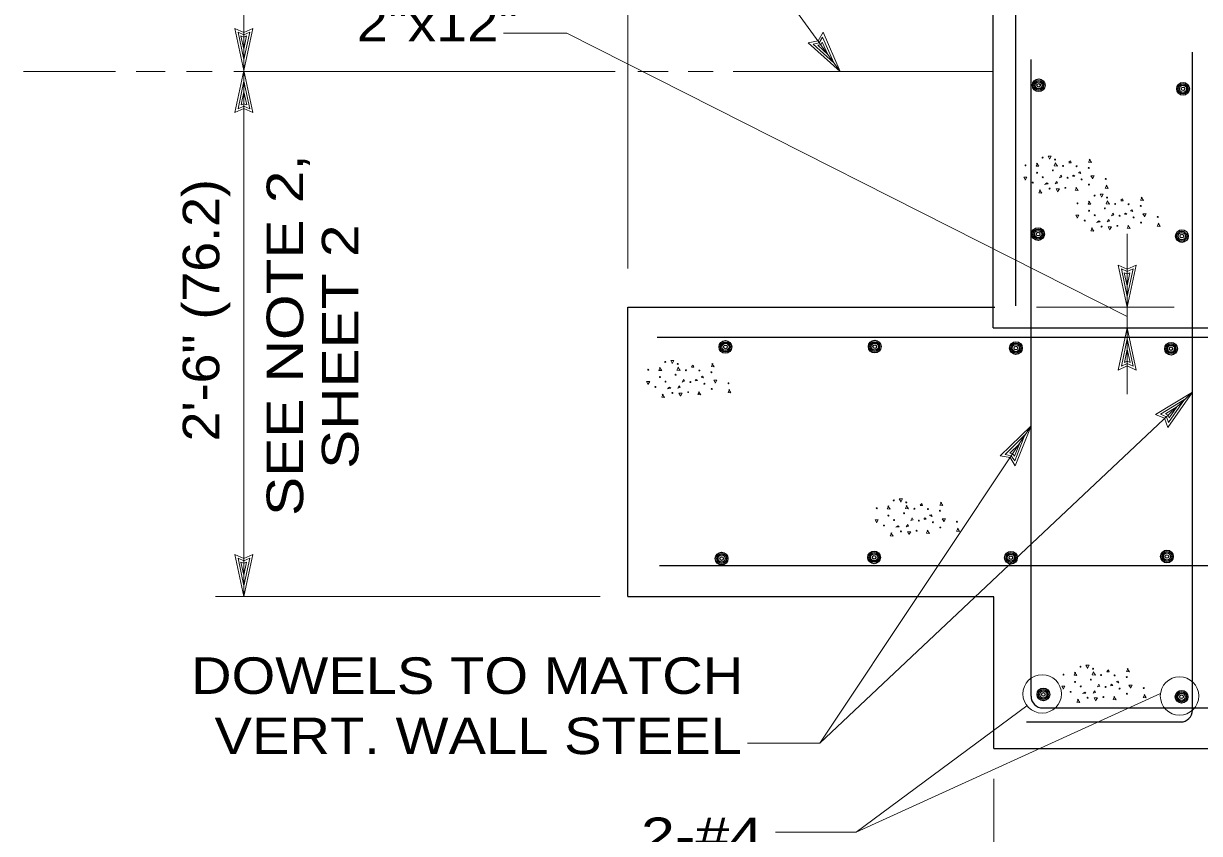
# Model space of a CAD drawing. Extents: x -28.1 to 13.9, y -16.1 to 13.9.
# Drawn here: x -10.95 to -6.926, y -12.515 to -9.744 of the extents above; entities that cross this region are included whole.
import ezdxf
from ezdxf.enums import TextEntityAlignment as Align

# ---------------------------------------------------------------- set-up
doc = ezdxf.new("R2010")
doc.units = 0
doc.header["$LTSCALE"] = 0.05
doc.layers.add('1', color=7, linetype='Continuous', lineweight=13)
doc.layers.add('2', color=7, linetype='Continuous', lineweight=13)

msp = doc.modelspace()

# ---------------------------------------------------------------- linework, layer by layer
at = {"layer": '1', "lineweight": 25}
for p, q in [((-7.63204, -10.78531), (-7.63204, -2.71131)), ((-7.55404, -10.70931), (-7.55404, -2.79231)), ((-6.95004, -12.09331), (-6.95004, -9.84231)), ((-7.50204, -12.04531), (-7.50204, -9.86731)), ((-8.88204, -11.70431), (-8.88204, -10.71431)), ((-8.88204, -10.71431), (-7.62604, -10.71431)), ((-8.78204, -10.81631), (-2.84404, -10.81631)), ((-7.63204, -10.78531), (-6.79104, -10.78531)), ((-8.77404, -11.59831), (-2.84304, -11.59831)), ((-8.88204, -11.70431), (-7.62904, -11.70431)), ((-7.62904, -12.22431), (-7.62904, -11.70531)), ((-7.46204, -12.08531), (-6.89104, -12.08531)), ((-7.51804, -12.13331), (-6.99004, -12.13331)), ((-7.62904, -12.22431), (-6.78704, -12.22431))]:
    msp.add_line(p, q, dxfattribs=at)
at = {"layer": '1'}
for p, q in [((-8.88204, -10.58231), (-8.88204, -7.58031)), ((-9.01904, -8.71531), (-8.15504, -9.90831)), ((-10.19604, -9.90431), (-10.22704, -9.76031)), ((-10.19604, -9.86731), (-10.21604, -9.77331)), ((-10.21604, -9.77331), (-10.19604, -9.78231)), ((-10.19604, -9.90431), (-10.16504, -9.76031)), ((-10.19604, -9.86731), (-10.17604, -9.77331)), ((-10.19604, -9.78231), (-10.17604, -9.77331)), ((-9.30704, -9.77731), (-9.09104, -9.77731)), ((-9.09104, -9.77731), (-7.17304, -10.74631)), ((-8.15504, -9.90831), (-8.21404, -9.77331)), ((-10.19604, -9.83131), (-10.20604, -9.78631)), ((-10.20604, -9.78631), (-10.19604, -9.79031)), ((-10.19604, -9.83131), (-10.18704, -9.78631)), ((-10.19604, -9.79031), (-10.18704, -9.78631)), ((-8.15504, -9.90831), (-8.26504, -9.81031)), ((-8.24804, -9.81431), (-8.22704, -9.80931)), ((-8.17704, -9.87831), (-8.24804, -9.81431)), ((-8.23204, -9.81831), (-8.22204, -9.81631)), ((-8.19804, -9.84931), (-8.23204, -9.81831)), ((-8.22704, -9.80931), (-8.21604, -9.79031)), ((-8.22204, -9.81631), (-8.21704, -9.80731)), ((-8.19804, -9.84931), (-8.21704, -9.80731)), ((-8.17704, -9.87831), (-8.21604, -9.79031)), ((-10.63504, -9.90831), (-10.95004, -9.90831)), ((-10.46504, -9.90831), (-10.56504, -9.90831)), ((-10.30404, -9.90831), (-10.39204, -9.90831)), ((-8.92504, -9.90831), (-10.23004, -9.90831)), ((-10.19604, -9.90431), (-10.22704, -10.04831)), ((-10.19604, -9.90431), (-10.16504, -10.04831)), ((-8.74404, -9.90831), (-8.84804, -9.90831)), ((-8.59004, -9.90831), (-8.67504, -9.90831)), ((-7.63204, -9.90831), (-8.52104, -9.90831)), ((-10.19604, -9.94131), (-10.21604, -10.03531)), ((-10.19604, -9.97731), (-10.20504, -10.02231)), ((-10.19604, -9.94131), (-10.17604, -10.03531)), ((-10.19604, -9.97731), (-10.18604, -10.02231)), ((-10.19604, -10.01831), (-10.20504, -10.02231)), ((-10.18604, -10.02231), (-10.19604, -10.01831)), ((-10.19604, -10.02631), (-10.21604, -10.03531)), ((-10.17604, -10.03531), (-10.19604, -10.02631)), ((-7.17304, -10.71431), (-7.20404, -10.57031)), ((-7.17304, -10.67731), (-7.19304, -10.58331)), ((-7.19304, -10.58331), (-7.17304, -10.59231)), ((-7.17304, -10.71431), (-7.14204, -10.57031)), ((-7.17304, -10.67731), (-7.15304, -10.58331)), ((-7.17304, -10.59231), (-7.15304, -10.58331)), ((-7.17304, -10.64131), (-7.18304, -10.59631)), ((-7.18304, -10.59631), (-7.17304, -10.60031)), ((-7.17304, -10.64131), (-7.16404, -10.59631)), ((-7.17304, -10.60031), (-7.16404, -10.59631)), ((-7.48304, -10.71431), (-7.01204, -10.71431)), ((-7.17304, -10.78531), (-7.20404, -10.92931)), ((-7.17304, -10.82231), (-7.19304, -10.91631)), ((-7.17304, -10.78531), (-7.14204, -10.92931)), ((-7.17304, -10.82231), (-7.15304, -10.91631)), ((-7.17304, -10.85831), (-7.18204, -10.90331)), ((-7.17304, -10.85831), (-7.16304, -10.90331)), ((-7.17304, -10.89931), (-7.18204, -10.90331)), ((-7.16304, -10.90331), (-7.17304, -10.89931)), ((-7.17304, -10.90731), (-7.19304, -10.91631)), ((-7.15304, -10.91631), (-7.17304, -10.90731)), ((-6.95004, -11.00531), (-8.22504, -12.20531)), ((-6.95004, -11.00531), (-7.07604, -11.08131)), ((-6.95004, -11.00531), (-7.03404, -11.12631)), ((-6.97704, -11.03031), (-7.05904, -11.08031)), ((-7.00304, -11.05531), (-7.04204, -11.07931)), ((-6.97704, -11.03031), (-7.03204, -11.10931)), ((-7.00304, -11.05531), (-7.02904, -11.09331)), ((-7.03904, -11.08931), (-7.05904, -11.08031)), ((-7.03304, -11.08331), (-7.04204, -11.07931)), ((-7.03204, -11.10931), (-7.03904, -11.08931)), ((-7.02904, -11.09331), (-7.03304, -11.08331)), ((-7.50204, -11.12031), (-7.60804, -11.22331)), ((-7.50204, -11.12031), (-7.55604, -11.25731)), ((-7.52304, -11.15131), (-7.59104, -11.21831)), ((-7.54204, -11.18131), (-7.57504, -11.21331)), ((-7.54204, -11.18131), (-7.55904, -11.22431)), ((-7.52304, -11.15131), (-7.55804, -11.24031)), ((-7.57004, -11.22231), (-7.59104, -11.21831)), ((-7.56504, -11.21531), (-7.57504, -11.21331)), ((-7.55804, -11.24031), (-7.57004, -11.22231)), ((-7.55904, -11.22431), (-7.56504, -11.21531)), ((-10.19604, -11.70431), (-10.22704, -11.56031)), ((-10.19604, -11.66731), (-10.21604, -11.57331)), ((-10.21604, -11.57331), (-10.19604, -11.58231)), ((-10.19604, -11.63131), (-10.20604, -11.58631)), ((-10.20604, -11.58631), (-10.19604, -11.59031)), ((-10.19604, -11.70431), (-10.16504, -11.56031)), ((-10.19604, -11.66731), (-10.17604, -11.57331)), ((-10.19604, -11.58231), (-10.17604, -11.57331)), ((-10.19604, -11.63131), (-10.18704, -11.58631)), ((-10.19604, -11.59031), (-10.18704, -11.58631)), ((-8.97704, -11.70431), (-10.29304, -11.70431)), ((-7.05904, -12.03631), (-8.10004, -12.51031)), ((-7.51604, -12.07831), (-8.10004, -12.51031)), ((-7.62904, -12.32831), (-7.62904, -12.78131)), ((-8.10004, -12.51031), (-8.37704, -12.51031))]:
    msp.add_line(p, q, dxfattribs=at)
for points in [[(-10.19604, -11.70431), (-10.19604, -9.90431), (-10.19604, -2.71031)], [(-10.22704, -9.76031), (-10.19604, -9.77431), (-10.16504, -9.76031)], [(-8.26504, -9.81031), (-8.23104, -9.80331), (-8.21404, -9.77331)], [(-10.16504, -10.04831), (-10.19604, -10.03431), (-10.22704, -10.04831)], [(-7.17304, -11.01231), (-7.17304, -10.78531), (-7.17304, -10.71431), (-7.17304, -10.46331)], [(-7.20404, -10.57031), (-7.17304, -10.58431), (-7.14204, -10.57031)], [(-7.14204, -10.92931), (-7.17304, -10.91531), (-7.20404, -10.92931)], [(-7.03404, -11.12631), (-7.04504, -11.09431), (-7.07604, -11.08131)], [(-7.50204, -11.12031), (-8.22504, -12.20531), (-8.47204, -12.20531)], [(-7.55604, -11.25731), (-7.57404, -11.22831), (-7.60804, -11.22331)], [(-10.22704, -11.56031), (-10.19604, -11.57431), (-10.16504, -11.56031)]]:
    msp.add_lwpolyline(points, dxfattribs=at)
at = {"layer": '1', "lineweight": 25}
for centre, radius in [((-7.47599, -9.95523), 0.02168), ((-7.47599, -9.95523), 0.01681), ((-7.47599, -9.95523), 0.01233), ((-7.47599, -9.95523), 0.00623), ((-6.98199, -9.96723), 0.02168), ((-6.98199, -9.96723), 0.01681), ((-6.98199, -9.96723), 0.01233), ((-6.98199, -9.96723), 0.00623), ((-7.47799, -10.46423), 0.02168), ((-7.47799, -10.46423), 0.01681), ((-7.47799, -10.46423), 0.01233), ((-7.47799, -10.46423), 0.00623), ((-6.98599, -10.47123), 0.02168), ((-6.98599, -10.47123), 0.01681), ((-6.98599, -10.47123), 0.01233), ((-6.98599, -10.47123), 0.00623), ((-8.54799, -10.85023), 0.02168), ((-8.54799, -10.85023), 0.01681), ((-8.54799, -10.85023), 0.01233), ((-8.54799, -10.85023), 0.00623), ((-8.03699, -10.84923), 0.02168), ((-8.03699, -10.84923), 0.01681), ((-8.03699, -10.84923), 0.01233), ((-8.03699, -10.84923), 0.00623), ((-7.55399, -10.85423), 0.02168), ((-7.55399, -10.85423), 0.01681), ((-7.55399, -10.85423), 0.01233), ((-7.55399, -10.85423), 0.00623), ((-7.02299, -10.85623), 0.02168), ((-7.02299, -10.85623), 0.01681), ((-7.02299, -10.85623), 0.01233), ((-7.02299, -10.85623), 0.00623), ((-8.03899, -11.57023), 0.02168), ((-7.57099, -11.57123), 0.02168), ((-7.03699, -11.56723), 0.02168), ((-8.56099, -11.57423), 0.02168), ((-8.56099, -11.57423), 0.01681), ((-8.56099, -11.57423), 0.01233), ((-8.56099, -11.57423), 0.00623), ((-8.03899, -11.57023), 0.01681), ((-8.03899, -11.57023), 0.01233), ((-8.03899, -11.57023), 0.00623), ((-7.57099, -11.57123), 0.01681), ((-7.57099, -11.57123), 0.01233), ((-7.57099, -11.57123), 0.00623), ((-7.03699, -11.56723), 0.01681), ((-7.03699, -11.56723), 0.01233), ((-7.03699, -11.56723), 0.00623), ((-7.45999, -12.03923), 0.02168), ((-7.45999, -12.03923), 0.01681), ((-7.45999, -12.03923), 0.01233), ((-6.98699, -12.04723), 0.02168), ((-6.98699, -12.04723), 0.01681), ((-7.45999, -12.03923), 0.00623), ((-6.98699, -12.04723), 0.01233), ((-6.98699, -12.04723), 0.00623)]:
    msp.add_circle(centre, radius, dxfattribs=at)
at = {"layer": '1'}
for centre in [(-7.46404, -12.03731), (-6.99404, -12.04431)]:
    msp.add_circle(centre, 0.0658, dxfattribs=at)
at = {"layer": '1', "lineweight": 25}
for centre, start, end in [((-7.46204, -12.04531), 180, 270), ((-6.99004, -12.09331), 270, 0)]:
    msp.add_arc(centre, 0.04, start, end, dxfattribs=at)
at = {"layer": '2'}
for p, q in [((-7.37304, -10.21831), (-7.36704, -10.21331)), ((-7.19504, -10.34831), (-7.18904, -10.34331)), ((-8.66404, -10.91731), (-8.65804, -10.91231)), ((-7.88204, -11.39131), (-7.87604, -11.38631)), ((-7.24304, -11.96031), (-7.23704, -11.95531))]:
    msp.add_line(p, q, dxfattribs=at)
for points in [[(-7.48004, -10.22131), (-7.48504, -10.23131), (-7.47504, -10.23231), (-7.48304, -10.22131)], [(-7.43904, -10.20631), (-7.44404, -10.19731), (-7.43304, -10.19731), (-7.43904, -10.20831)], [(-7.41804, -10.22031), (-7.42304, -10.23031), (-7.41204, -10.23131), (-7.42004, -10.22031)], [(-7.36704, -10.21331), (-7.36504, -10.22031), (-7.37304, -10.22031)], [(-7.30004, -10.20831), (-7.30504, -10.21831), (-7.29504, -10.21931), (-7.30304, -10.20831)], [(-7.34004, -10.25331), (-7.33504, -10.25131), (-7.33204, -10.25731), (-7.34004, -10.25431)], [(-7.52204, -10.27731), (-7.52704, -10.26931), (-7.51604, -10.26931), (-7.52204, -10.27931)], [(-7.45304, -10.29231), (-7.44804, -10.28931), (-7.44404, -10.29231), (-7.45604, -10.29431)], [(-7.36004, -10.26631), (-7.35704, -10.26231), (-7.35204, -10.26631), (-7.35904, -10.26731)], [(-7.29204, -10.27331), (-7.29704, -10.26531), (-7.28604, -10.26531), (-7.29204, -10.27531)], [(-7.24304, -10.29731), (-7.24804, -10.30731), (-7.23804, -10.30831), (-7.24504, -10.29731)], [(-7.47004, -10.31331), (-7.47504, -10.32331), (-7.46504, -10.32431), (-7.47304, -10.31331)], [(-7.41104, -10.31831), (-7.41604, -10.30931), (-7.40504, -10.30931), (-7.41104, -10.31931)], [(-7.34604, -10.30431), (-7.35104, -10.31431), (-7.34104, -10.31531), (-7.34904, -10.30431)], [(-7.26104, -10.33631), (-7.26604, -10.32731), (-7.25504, -10.32731), (-7.26104, -10.33831)], [(-7.12204, -10.33831), (-7.12704, -10.34831), (-7.11704, -10.34931), (-7.12504, -10.33831)], [(-7.30204, -10.35131), (-7.30704, -10.36131), (-7.29704, -10.36231), (-7.30504, -10.35131)], [(-7.24004, -10.35031), (-7.24504, -10.36031), (-7.23404, -10.36131), (-7.24204, -10.35031)], [(-7.18904, -10.34331), (-7.18704, -10.35031), (-7.19504, -10.35031)], [(-7.16204, -10.38331), (-7.15704, -10.38131), (-7.15404, -10.38731), (-7.16204, -10.38431)], [(-7.34404, -10.40731), (-7.34904, -10.39931), (-7.33804, -10.39931), (-7.34404, -10.40931)], [(-7.27504, -10.42231), (-7.27004, -10.41931), (-7.26604, -10.42231), (-7.27804, -10.42431)], [(-7.18204, -10.39631), (-7.17904, -10.39231), (-7.17404, -10.39631), (-7.18104, -10.39731)], [(-7.11404, -10.40331), (-7.11904, -10.39531), (-7.10804, -10.39531), (-7.11404, -10.40531)], [(-7.29204, -10.44331), (-7.29704, -10.45331), (-7.28704, -10.45431), (-7.29504, -10.44331)], [(-7.23304, -10.44831), (-7.23804, -10.43931), (-7.22704, -10.43931), (-7.23304, -10.44931)], [(-7.16804, -10.43431), (-7.17304, -10.44431), (-7.16304, -10.44531), (-7.17104, -10.43431)], [(-7.06504, -10.42731), (-7.07004, -10.43731), (-7.06004, -10.43831), (-7.06704, -10.42731)], [(-8.73004, -10.90531), (-8.73504, -10.89631), (-8.72404, -10.89631), (-8.73004, -10.90731)], [(-8.77104, -10.92031), (-8.77604, -10.93031), (-8.76604, -10.93131), (-8.77404, -10.92031)], [(-8.70904, -10.91931), (-8.71404, -10.92931), (-8.70304, -10.93031), (-8.71104, -10.91931)], [(-8.65804, -10.91231), (-8.65604, -10.91931), (-8.66404, -10.91931)], [(-8.59104, -10.90731), (-8.59604, -10.91731), (-8.58604, -10.91831), (-8.59404, -10.90731)], [(-8.81304, -10.97631), (-8.81804, -10.96831), (-8.80704, -10.96831), (-8.81304, -10.97831)], [(-8.65104, -10.96531), (-8.64804, -10.96131), (-8.64304, -10.96531), (-8.65004, -10.96631)], [(-8.63104, -10.95231), (-8.62604, -10.95031), (-8.62304, -10.95631), (-8.63104, -10.95331)], [(-8.58304, -10.97231), (-8.58804, -10.96431), (-8.57704, -10.96431), (-8.58304, -10.97431)], [(-8.76104, -11.01231), (-8.76604, -11.02231), (-8.75604, -11.02331), (-8.76404, -11.01231)], [(-8.74404, -10.99131), (-8.73904, -10.98831), (-8.73504, -10.99131), (-8.74704, -10.99331)], [(-8.70204, -11.01731), (-8.70704, -11.00831), (-8.69604, -11.00831), (-8.70204, -11.01831)], [(-8.63704, -11.00331), (-8.64204, -11.01331), (-8.63204, -11.01431), (-8.64004, -11.00331)], [(-8.53404, -10.99631), (-8.53904, -11.00631), (-8.52904, -11.00731), (-8.53604, -10.99631)], [(-7.94804, -11.37931), (-7.95304, -11.37031), (-7.94204, -11.37031), (-7.94804, -11.38131)], [(-7.87604, -11.38631), (-7.87404, -11.39331), (-7.88204, -11.39331)], [(-7.80904, -11.38131), (-7.81404, -11.39131), (-7.80404, -11.39231), (-7.81204, -11.38131)], [(-7.98904, -11.39431), (-7.99404, -11.40431), (-7.98404, -11.40531), (-7.99204, -11.39431)], [(-7.92704, -11.39331), (-7.93204, -11.40331), (-7.92104, -11.40431), (-7.92904, -11.39331)], [(-7.84904, -11.42631), (-7.84404, -11.42431), (-7.84104, -11.43031), (-7.84904, -11.42731)], [(-8.03104, -11.45031), (-8.03604, -11.44231), (-8.02504, -11.44231), (-8.03104, -11.45231)], [(-7.96204, -11.46531), (-7.95704, -11.46231), (-7.95304, -11.46531), (-7.96504, -11.46731)], [(-7.86904, -11.43931), (-7.86604, -11.43531), (-7.86104, -11.43931), (-7.86804, -11.44031)], [(-7.80104, -11.44631), (-7.80604, -11.43831), (-7.79504, -11.43831), (-7.80104, -11.44831)], [(-7.97904, -11.48631), (-7.98404, -11.49631), (-7.97404, -11.49731), (-7.98204, -11.48631)], [(-7.92004, -11.49131), (-7.92504, -11.48231), (-7.91404, -11.48231), (-7.92004, -11.49231)], [(-7.85504, -11.47731), (-7.86004, -11.48731), (-7.85004, -11.48831), (-7.85804, -11.47731)], [(-7.75204, -11.47031), (-7.75704, -11.48031), (-7.74704, -11.48131), (-7.75404, -11.47031)], [(-7.30904, -11.94831), (-7.31404, -11.93931), (-7.30304, -11.93931), (-7.30904, -11.95031)], [(-7.17004, -11.95031), (-7.17504, -11.96031), (-7.16504, -11.96131), (-7.17304, -11.95031)], [(-7.35004, -11.96331), (-7.35504, -11.97331), (-7.34504, -11.97431), (-7.35304, -11.96331)], [(-7.28804, -11.96231), (-7.29304, -11.97231), (-7.28204, -11.97331), (-7.29004, -11.96231)], [(-7.23704, -11.95531), (-7.23504, -11.96231), (-7.24304, -11.96231)], [(-7.39204, -12.01931), (-7.39704, -12.01131), (-7.38604, -12.01131), (-7.39204, -12.02131)], [(-7.32304, -12.03431), (-7.31804, -12.03131), (-7.31404, -12.03431), (-7.32604, -12.03631)], [(-7.23004, -12.00831), (-7.22704, -12.00431), (-7.22204, -12.00831), (-7.22904, -12.00931)], [(-7.21004, -11.99531), (-7.20504, -11.99331), (-7.20204, -11.99931), (-7.21004, -11.99631)], [(-7.16204, -12.01531), (-7.16704, -12.00731), (-7.15604, -12.00731), (-7.16204, -12.01731)], [(-7.34004, -12.05531), (-7.34504, -12.06531), (-7.33504, -12.06631), (-7.34304, -12.05531)], [(-7.28104, -12.06031), (-7.28604, -12.05131), (-7.27504, -12.05131), (-7.28104, -12.06131)], [(-7.21604, -12.04631), (-7.22104, -12.05631), (-7.21104, -12.05731), (-7.21904, -12.04631)], [(-7.11304, -12.03931), (-7.11804, -12.04931), (-7.10804, -12.05031), (-7.11504, -12.03931)]]:
    msp.add_lwpolyline(points, dxfattribs=at)
for points in [[(-7.42004, -10.29231), (-7.41504, -10.28431), (-7.41204, -10.29031)], [(-7.40504, -10.27131), (-7.40004, -10.26231), (-7.39704, -10.26831)], [(-7.24204, -10.42231), (-7.23704, -10.41431), (-7.23404, -10.42031)], [(-7.22704, -10.40131), (-7.22204, -10.39231), (-7.21904, -10.39831)], [(-8.71104, -10.99131), (-8.70604, -10.98331), (-8.70304, -10.98931)], [(-8.69604, -10.97031), (-8.69104, -10.96131), (-8.68804, -10.96731)], [(-7.92904, -11.46531), (-7.92404, -11.45731), (-7.92104, -11.46331)], [(-7.91404, -11.44431), (-7.90904, -11.43531), (-7.90604, -11.44131)], [(-7.29004, -12.03431), (-7.28504, -12.02631), (-7.28204, -12.03231)], [(-7.27504, -12.01331), (-7.27004, -12.00431), (-7.26704, -12.01031)]]:
    msp.add_lwpolyline(points, close=True, dxfattribs=at)
for centre in [(-7.46279, -10.20244), (-7.42004, -10.20919), (-7.52104, -10.22919), (-7.48129, -10.25444), (-7.42754, -10.24619), (-7.39229, -10.23094), (-7.34604, -10.23194), (-7.30479, -10.23769), (-7.49654, -10.28819), (-7.46204, -10.26969), (-7.37704, -10.27144), (-7.32904, -10.27719), (-7.30379, -10.29494), (-7.24654, -10.27544), (-7.43854, -10.30844), (-7.38454, -10.30594), (-7.28479, -10.33244), (-7.24204, -10.33919), (-7.34304, -10.35919), (-7.30329, -10.38444), (-7.24954, -10.37619), (-7.21429, -10.36094), (-7.16804, -10.36194), (-7.12679, -10.36769), (-7.31854, -10.41819), (-7.28404, -10.39969), (-7.19904, -10.40144), (-7.15104, -10.40719), (-7.06854, -10.40544), (-7.26054, -10.43844), (-7.20654, -10.43594), (-7.12579, -10.42494), (-8.75379, -10.90144), (-8.81204, -10.92819), (-8.71854, -10.94519), (-8.71104, -10.90819), (-8.68329, -10.92994), (-8.63704, -10.93094), (-8.59579, -10.93669), (-8.78754, -10.98719), (-8.77229, -10.95344), (-8.75304, -10.96869), (-8.66804, -10.97044), (-8.62004, -10.97619), (-8.53754, -10.97444), (-8.72954, -11.00744), (-8.67554, -11.00494), (-8.59479, -10.99394), (-7.97179, -11.37544), (-7.92904, -11.38219), (-8.03004, -11.40219), (-7.99029, -11.42744), (-7.93654, -11.41919), (-7.90129, -11.40394), (-7.85504, -11.40494), (-7.81379, -11.41069), (-8.00554, -11.46119), (-7.97104, -11.44269), (-7.88604, -11.44444), (-7.83804, -11.45019), (-7.81279, -11.46794), (-7.75554, -11.44844), (-7.94754, -11.48144), (-7.89354, -11.47894), (-7.33279, -11.94444), (-7.29004, -11.95119), (-7.39104, -11.97119), (-7.29754, -11.98819), (-7.26229, -11.97294), (-7.21604, -11.97394), (-7.17479, -11.97969), (-7.36654, -12.03019), (-7.35129, -11.99644), (-7.33204, -12.01169), (-7.24704, -12.01344), (-7.19904, -12.01919), (-7.11654, -12.01744), (-7.30854, -12.05044), (-7.25454, -12.04794), (-7.17379, -12.03694)]:
    msp.add_circle(centre, 0.00162, dxfattribs=at)

# ---------------------------------------------------------------- texts
at = {"layer": '1', "width": 1.15}
for s, p in [('2"x12"', (-9.53318, -9.80431)), ('DOWELS TO MATCH', (-9.43177, -12.03731))]:
    msp.add_text(s, height=0.125, dxfattribs=at).set_placement(p, align=Align.CENTER)
at = {"layer": '1'}
for s, width, p in [('SEE NOTE 2,', 1.2, (-9.99304, -10.80986)), ('2\'-6" (76.2)', 1.1, (-10.28004, -10.72495)), ('SHEET 2', 1.2, (-9.80404, -10.84942))]:
    msp.add_text(s, height=0.125, rotation=90, dxfattribs=dict(at, width=width)).set_placement(p, align=Align.CENTER)
for s, width, p in [('VERT. WALL STEEL', 1.15, (-8.49116, -12.24331)), ('2-#4', 1.25, (-8.41883, -12.58531))]:
    msp.add_text(s, height=0.125, dxfattribs=dict(at, width=width)).set_placement(p, align=Align.RIGHT)

doc.saveas('drawing.dxf')
